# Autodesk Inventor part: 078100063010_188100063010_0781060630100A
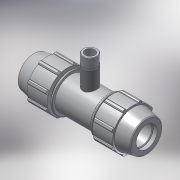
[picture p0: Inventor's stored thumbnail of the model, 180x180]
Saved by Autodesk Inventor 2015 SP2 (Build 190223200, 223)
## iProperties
Created: 2017-02
Part Number: 078100063010_188100063010_0781060630100A
Material: PVC-Piping
Description: PLASSON COUPLER WITH RISER 63-1"
Document SubType Name: Modeling
Designer: KIM
Mass: 92.6774 g
Surface Area: 199.44 cm^2
Volume: 66.1981 cm^3
Density: 1.4 g/cm^3
Appearance: Smooth - White
Author: Кирилл
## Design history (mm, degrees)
derived "07810.ipt"
feature "Solid1::07810.ipt"
feature "Solid2::07810.ipt"
tag "TaggingFeature1"
body "Solid1"
other parameters: "d2" = 63, "d4" = 11.25, "d5" = 32.4, "d7" = 113, "d11" = 4.5, "d13" = 120 deg, "d14" = 81.9, "d15" = 12 deg, "d16" = 98.31, "d18" = 3.15, "d19" = 35 deg, "d20" = 17.5 deg, "d21" = 105.09, "d23" = 0, "d25" = 360 deg, "d27" = 2.26, "d33" = 1.26, "d42" = 48.6, "d43" = 3.39, "d46" = 1.89, "d68" = 4.5, "d72" = 95, "d73" = 33.249, "d76" = 23.2743, "d77" = 24, "d80" = 0.99747, "d91" = 84.75, "d95" = 56.7, "d101" = 0, "d103" = 0, "d105" = 0, "d106" = 33.91398, "d_" = 63, "E_" = 113, "A_" = 95, "R_" = 33.249
